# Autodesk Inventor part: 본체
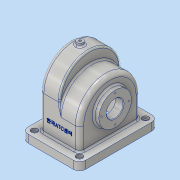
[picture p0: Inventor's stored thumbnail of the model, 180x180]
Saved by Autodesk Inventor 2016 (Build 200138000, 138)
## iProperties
Created: 2017-11
Part Number: 본체
Material: 알루미늄 6061
Document SubType Name: Modeling
Designer: 605-15
Mass: 1091.76 g
Surface Area: 1182.01 cm^2
Volume: 404.355 cm^3
Density: 2.7 g/cm^3
Appearance: 알루미늄 - 평지
Author: 605-15
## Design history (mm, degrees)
sketch "스케치1"
  geometry: L1 (55, -75)-(-55, -75); L2 (-55, -75)-(-55, 75); L3 (-55, 75)-(55, 75); L4 (55, 75)-(55, -75); L5 (55, -75)-(-55, 75); L6 (-55, -75)-(55, 75); 1 further point
  constraints: 12 end point, 2 midpoint, 2 parallel, 1 horizontal, 1 perpendicular
  dimensions: "d0" = 110 distance between parallel lines of L4 L2; "d1" = 150 distance of L3.end L1.start
extrude "돌출1" new body sketch "스케치1" distance "d2" = 15; taper "d3" = 0 deg
node "작업 평면1"
sketch "스케치2"
  geometry: 1 further point
sketch "스케치3"
  geometry: L1 (15, 0)-(15, 150) reference; L2 (15, 133)-(80, 133); L3 (80, 17)-(15, 17); C1 r 0.532 at (83.077, 71.826); A1 r 58 centre (80, 75) between (80, 17) and (80, 133); 1 further point
  constraints: 4 end point, 2 centre point, 2 point on circle, 2 point on line, 1 horizontal, 1 horizontal alignment, 1 parallel, 1 perpendicular, 1 tangent
  dimensions: "d5" = 80 distance of point (0, 75) A1.centre; "d6" = 58 radius of A1
extrude "돌출2" join sketch "스케치3" distance "d7" = 38; taper "d8" = 0 deg
sketch "스케치4"
  geometry: A1 r 58 centre (80, 75) between (80, 17) and (80, 133) reference; 1 further point
sketch "스케치5"
  geometry: L1 (0, 150)-(0, 0) reference; C1 r 37.5 at (65, 75); A1 r 58 centre (80, 75) between (80, 17) and (80, 133) reference; 1 further point
  constraints: 1 centre point, 1 horizontal alignment
  dimensions: "d9" = 65 distance from line of L1 C1.centre; "d10" = 75 diameter of C1
extrude "돌출3" join sketch "스케치5" distance "d11" = 9; taper "d12" = 0 deg
sketch "스케치6"
  geometry: L1 (-15, 17)-(-80, 17) reference; L2 (-80, 133)-(-15, 133) reference; L3 (0, 150)-(0, 0) reference; L4 (-15, 0)-(-15, 150) reference; L5 (-15, 17)-(-80, 17) reference; L6 (-57, 17)-(-15, 17); L7 (-80, 133)-(-15, 133) reference; L8 (-57, 133)-(-15, 133); L9 (-15, 17)-(-15, 133) reference; L10 (-15, 133)-(-15, 17); A1 r 58 centre (-57, 75) between (-57, 133) and (-57, 17); 2 further points
  constraints: 6 end point, 3 collinear, 2 point on circle, 2 point on line, 1 centre point, 1 horizontal alignment, 1 midpoint
  dimensions: "d13" = 57 distance from line of L3 A1.centre; "d14" = 116 diameter of A1
extrude "돌출4" join sketch "스케치6" distance "d15" = 38; taper "d16" = 0 deg
sketch "스케치7"
  geometry: L1 (0, 0)-(0, 150) reference; C1 r 31 at (-65, 75); 1 further point
  constraints: 1 centre point, 1 horizontal alignment
  dimensions: "d17" = 65 distance from line of L1 C1.centre; "d18" = 62 diameter of C1
extrude "돌출5" join sketch "스케치7" distance "d19" = 10; taper "d20" = 0 deg
node "작업 평면2"
sketch "스케치8"
  geometry: L1 (80, 128)-(0, 128); L2 (0, 150)-(0, 0) reference; L3 (80, 22)-(0, 22); A1 r 58 centre (80, 75) between (80, 17) and (80, 133) reference; A2 r 53 centre (80, 75) between (80, 22) and (80, 128); 1 further point
  constraints: 4 end point, 2 point on circle, 2 point on line, 1 centre point, 1 horizontal, 1 parallel
  dimensions: "d22" = 5 radial gap between concentric circles of A1 A2; "d23" = 53 distance of L1.end point (0, 75); "d24" = 53 distance of L3.end point (0, 75)
extrude "돌출6" cut sketch "스케치8" distance "d25" = 28; taper "d26" = 0 deg
sketch "스케치9"
  geometry: L1 (0, 150)-(0, 0) reference; L2 (57, 128)-(0, 128); L3 (57, 22)-(0, 22); A1 r 58 centre (57, 75) between (57, 17) and (57, 133) reference; A2 r 53 centre (57, 75) between (57, 22) and (57, 128); 1 further point
  constraints: 4 end point, 2 perpendicular, 2 point on circle, 2 point on line, 1 centre point
  dimensions: "d27" = 5 radial gap between concentric circles of A1 A2; "d28" = 53 distance of point (0, 75) L2.end; "d29" = 53 distance of L3.end point (0, 75)
extrude "돌출7" cut sketch "스케치9" distance "d30" = 38; taper "d31" = 0 deg
sketch "스케치10"
  geometry: 1 further point
hole "구멍1" diameter "d34" = 32; stored, may be unused: countersink angle "d38" = 90 deg, drill point angle "d40" = 118 deg; dims "d32" = 10, "d33" = 10, "d35" = 6, "d36" = 4, "d37" = 2, "d39" = 8
sketch "스케치11"
  geometry: 1 further point
sketch "스케치12"
  geometry: C1 r 37.5 at (0, 0) reference; 2 further points
  dimensions: "d41" = 29 distance of C1.centre point (29, 0)
hole "구멍2" sketch "스케치12" at (29, 0) diameter "d42" = 2.459; stored, may be unused: countersink angle "d46" = 90 deg, drill point angle "d48" = 118 deg; dims "d43" = 6, "d44" = 4, "d45" = 2, "d47" = 8
sketch "스케치13"
  geometry: C1 r 31 at (0, 0) reference; 2 further points
  constraints: 1 horizontal alignment
  dimensions: "d52" = 26 distance of C1.centre point (-26, 0)
hole "구멍3" sketch "스케치13" at (-26, 0) diameter "d53" = 2.459; stored, may be unused: countersink angle "d57" = 90 deg, drill point angle "d59" = 118 deg; dims "d54" = 6, "d55" = 4, "d56" = 2, "d58" = 8
node "작업 평면3"
sketch "스케치14"
  geometry: L1 (38, -58)-(38, 58) reference; C1 r 6 at (19, 0); 1 further point
  constraints: 1 centre point, 1 horizontal alignment
  dimensions: "d64" = 19 distance from line of L1 C1.centre; "d65" = 12 diameter of C1
extrude "돌출8" join sketch "스케치14" stored distance "d66" = 38; taper "d67" = 0 deg
hole "구멍4" diameter "d70" = 4.459; stored, may be unused: countersink angle "d74" = 90 deg, drill point angle "d76" = 118 deg; dims "d71" = 20, "d72" = 4, "d73" = 2, "d75" = 8, "d89" = 10, "d90" = 10
fillet "모깎기1" dims "d77" = 8
fillet "모깎기2" dims "d78" = 3
fillet "모깎기3" dims "d79" = 3
chamfer "모따기1" distance "d80" = 1; stored, may be unused: second distance "d81" = 2, angle "d82" = 45 deg
fillet "모깎기4" dims "d83" = 3
fillet "모깎기5" dims "d84" = 3
sketch "스케치15"
  geometry: 1 further point
sketch "스케치16"
  geometry: L1 (-25, -18)-(85, -18) reference; L2 (-8, 62)-(-8, 0) reference; 2 further points
  constraints: 1 other
  dimensions: "d85" = 40 distance from line of L1 point (30, 22); "d86" = 38 distance from line of point (30, 22) L2
feature "엠보싱1" sketch "스케치16" dims "d87" = 0.5, "d88" = 0
fillet "모깎기6" dims "d91" = 12
sketch "스케치17"
  geometry: A1 r 12 centre (-43, -63) between (-55, -63) and (-43, -75) reference; A2 r 12 centre (-43, 63) between (-43, 75) and (-55, 63) reference; A3 r 12 centre (43, 63) between (55, 63) and (43, 75) reference; A4 r 12 centre (43, -63) between (43, -75) and (55, -63) reference; 5 further points
  constraints: 4 coincident
hole "구멍5" sketch "스케치17" at (-43, -63), (-43, 63), (43, 63), (43, -63) diameter "d92" = 5; stored, may be unused: countersink angle "d96" = 90 deg, drill point angle "d98" = 118 deg; dims "d93" = 6, "d94" = 12, "d95" = 5, "d97" = 8
node "솔리드1"
pattern_circular "원형 패턴1" dims angle "d50" = 360 deg
pattern_circular "원형 패턴2" dims angle "d61" = 360 deg
other parameters: "d4" = -55, "d21" = -5, "d63" = -144
